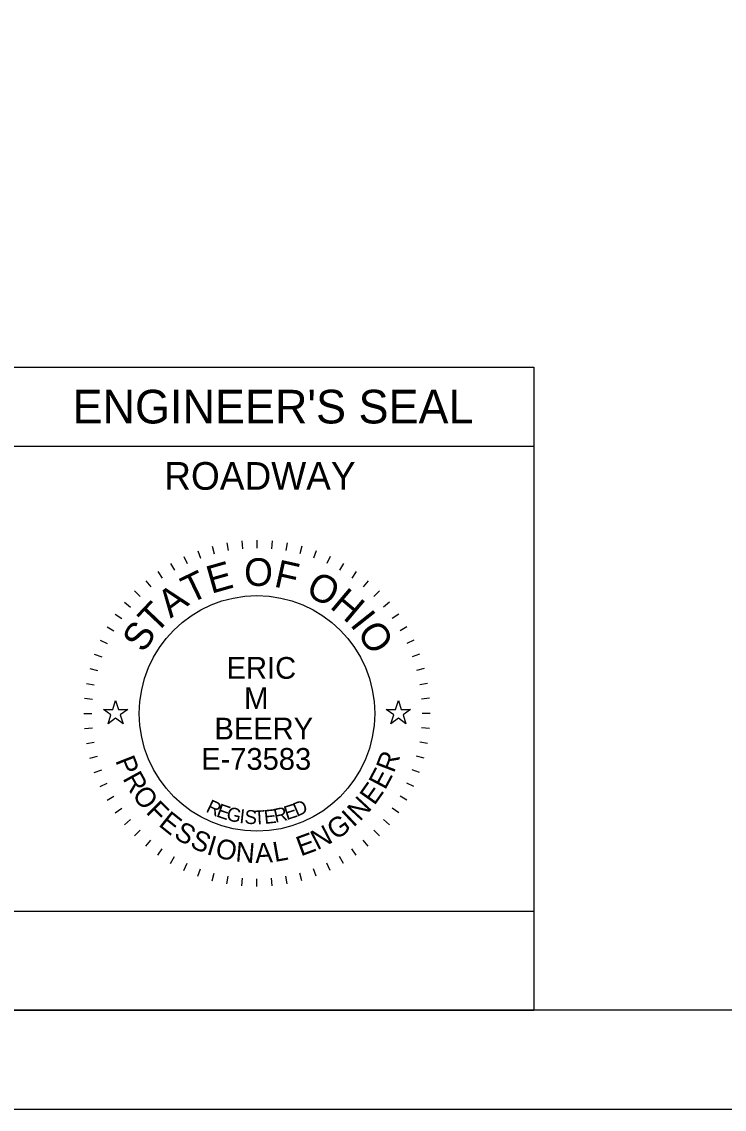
# Model space of a CAD drawing. Extents: x 0 to 34, y 0 to 22.
# Drawn here: x 23.81 to 27.36, y 0 to 5.49 of the extents above; entities that cross this region are included whole.
import ezdxf

# ---------------------------------------------------------------- set-up
doc = ezdxf.new("R2010")
doc.units = 0
for name, color, linetype in [('Default', 7, 'Continuous'), ('SH_Border', 7, 'Continuous'), ('SH_Cut_Line', 7, 'Continuous'), ('SH_Data', 7, 'Continuous')]:
    doc.layers.add(name, color=color, linetype=linetype)

msp = doc.modelspace()

# ---------------------------------------------------------------- linework, layer by layer
at = {"layer": 'Default'}
for points in [[(24.2236, 2.02), (24.2705, 2.02), (24.285, 2.0645), (24.2995, 2.02), (24.3464, 2.02), (24.3085, 1.9924), (24.323, 1.9478), (24.285, 1.9754), (24.247, 1.9478), (24.2615, 1.9924)], [(25.6536, 2.02), (25.7005, 2.02), (25.715, 2.0645), (25.7295, 2.02), (25.7764, 2.02), (25.7385, 1.9924), (25.753, 1.9478), (25.715, 1.9754), (25.677, 1.9478), (25.6915, 1.9924)]]:
    msp.add_lwpolyline(points, close=True, dxfattribs=at)
at = {"layer": 'SH_Border'}
msp.add_lwpolyline([(1.5, 21.5), (33.5, 21.5), (33.5, 0.5), (1.5, 0.5)], close=True, dxfattribs=at)
at = {"layer": 'SH_Cut_Line'}
msp.add_lwpolyline([(0, 0), (34, 0), (34, 22), (0, 22)], close=True, dxfattribs=at)
at = {"layer": 'SH_Data'}
for p, q in [((23.6, 3.75), (26.4, 3.75)), ((26.4, 3.75), (26.4, 0.5)), ((23.6, 3.35), (26.4, 3.35)), ((24.8481, 2.8617), (24.855, 2.8223)), ((24.9237, 2.8717), (24.9272, 2.8318)), ((25, 2.875), (25, 2.835)), ((25.0763, 2.8717), (25.0728, 2.8318)), ((25.1519, 2.8617), (25.145, 2.8223)), ((24.7007, 2.8222), (24.7144, 2.7846)), ((24.7735, 2.8452), (24.7839, 2.8065)), ((25.2265, 2.8452), (25.2161, 2.8065)), ((25.2993, 2.8222), (25.2856, 2.7846)), ((24.5625, 2.7578), (24.5825, 2.7231)), ((24.6302, 2.793), (24.6471, 2.7568)), ((25.3698, 2.793), (25.3529, 2.7568)), ((25.4375, 2.7578), (25.4175, 2.7231)), ((24.4981, 2.7168), (24.5211, 2.684)), ((25.5019, 2.7168), (25.4789, 2.684)), ((24.4376, 2.6703), (24.4633, 2.6396)), ((25.5624, 2.6703), (25.5367, 2.6396)), ((24.3813, 2.6187), (24.4096, 2.5904)), ((25.6187, 2.6187), (25.5904, 2.5904)), ((24.3297, 2.5624), (24.3604, 2.5367)), ((25.6703, 2.5624), (25.6396, 2.5367)), ((24.2832, 2.5019), (24.316, 2.4789)), ((25.7168, 2.5019), (25.684, 2.4789)), ((24.2422, 2.4375), (24.2769, 2.4175)), ((25.7578, 2.4375), (25.7231, 2.4175)), ((24.207, 2.3698), (24.2432, 2.3529)), ((25.793, 2.3698), (25.7568, 2.3529)), ((24.1778, 2.2993), (24.2154, 2.2856)), ((25.8222, 2.2993), (25.7846, 2.2856)), ((24.1548, 2.2265), (24.1935, 2.2161)), ((25.8452, 2.2265), (25.8065, 2.2161)), ((24.1383, 2.1519), (24.1777, 2.145)), ((25.8617, 2.1519), (25.8223, 2.145)), ((24.1283, 2.0763), (24.1682, 2.0728)), ((25.8717, 2.0763), (25.8318, 2.0728)), ((24.125, 2), (24.165, 2)), ((25.875, 2), (25.835, 2)), ((24.1283, 1.9237), (24.1682, 1.9272)), ((25.8717, 1.9237), (25.8318, 1.9272)), ((24.1383, 1.8481), (24.1777, 1.855)), ((25.8617, 1.8481), (25.8223, 1.855)), ((24.1548, 1.7735), (24.1935, 1.7839)), ((25.8452, 1.7735), (25.8065, 1.7839)), ((24.1778, 1.7007), (24.2154, 1.7144)), ((25.8222, 1.7007), (25.7846, 1.7144)), ((24.207, 1.6302), (24.2432, 1.6471)), ((25.793, 1.6302), (25.7568, 1.6471)), ((24.2422, 1.5625), (24.2769, 1.5825)), ((25.7578, 1.5625), (25.7231, 1.5825)), ((24.2832, 1.4981), (24.316, 1.5211)), ((25.7168, 1.4981), (25.684, 1.5211)), ((24.3297, 1.4376), (24.3604, 1.4633)), ((25.6703, 1.4376), (25.6396, 1.4633)), ((24.3813, 1.3813), (24.4096, 1.4096)), ((25.6187, 1.3813), (25.5904, 1.4096)), ((24.4376, 1.3297), (24.4633, 1.3604)), ((25.5624, 1.3297), (25.5367, 1.3604)), ((24.4981, 1.2832), (24.5211, 1.316)), ((24.5625, 1.2422), (24.5825, 1.2769)), ((25.4375, 1.2422), (25.4175, 1.2769)), ((25.5019, 1.2832), (25.4789, 1.316)), ((24.6302, 1.207), (24.6471, 1.2432)), ((24.7007, 1.1778), (24.7144, 1.2154)), ((25.2993, 1.1778), (25.2856, 1.2154)), ((25.3698, 1.207), (25.3529, 1.2432)), ((24.7735, 1.1548), (24.7839, 1.1935)), ((24.8481, 1.1383), (24.855, 1.1777)), ((24.9237, 1.1283), (24.9272, 1.1682)), ((25, 1.125), (25, 1.165)), ((25.0763, 1.1283), (25.0728, 1.1682)), ((25.1519, 1.1383), (25.145, 1.1777)), ((25.2265, 1.1548), (25.2161, 1.1935)), ((23.6, 0.5), (26.4, 0.5))]:
    msp.add_line(p, q, dxfattribs=at)
msp.add_lwpolyline([(23.6, 0.5), (23.6, 1), (26.4, 1), (26.4, 0.5)], close=True, dxfattribs=at)
msp.add_circle((25, 2), 0.595, dxfattribs=at)

# ---------------------------------------------------------------- texts
for s, height, p in [("ENGINEER'S SEAL", 0.17, (24.0676, 3.465)), ('ROADWAY', 0.14, (24.5311, 3.13)), ('ERIC', 0.11, (24.8465, 2.1749)), ('M', 0.11, (24.9348, 2.0216)), ('BEERY', 0.11, (24.7848, 1.8684)), ('E-73583', 0.11, (24.7177, 1.7151))]:
    msp.add_text(s, height=height, dxfattribs=at).set_placement(p)
for s, height, rotation, p in [('E', 0.14, 15.7571, (24.7684, 2.6038)), ('O', 0.14, 359.7812, (24.9347, 2.6443)), ('F', 0.14, 347.4362, (25.0811, 2.6417)), ('T', 0.14, 25.7167, (24.6616, 2.5518)), ('O', 0.14, 332.2586, (25.2398, 2.6015)), ('A', 0.14, 36.4747, (24.5634, 2.4781)), ('H', 0.14, 319.9136, (25.3632, 2.5361)), ('T', 0.14, 46.4344, (24.4883, 2.3964)), ('I', 0.14, 308.367, (25.4665, 2.4483)), ('S', 0.14, 57.1924, (24.4281, 2.3014)), ('O', 0.14, 303.1491, (25.5021, 2.4089)), ('P', 0.1, 291.494, (24.2823, 1.7621)), ('R', 0.1, 69.2322, (25.6919, 1.6954)), ('R', 0.1, 298.7311, (24.319, 1.6717)), ('E', 0.1, 61.9951, (25.6476, 1.6098)), ('E', 0.1, 54.758, (25.5933, 1.5314)), ('O', 0.1, 306.4666, (24.3655, 1.5883)), ('F', 0.1, 314.7068, (24.4343, 1.4983)), ('R', 0.07, 334.487, (24.7375, 1.5051)), ('E', 0.07, 341.04, (24.7906, 1.4801)), ('E', 0.07, 17.6836, (25.1498, 1.4602)), ('D', 0.07, 23.3052, (25.201, 1.477)), ('N', 0.1, 47.0224, (25.5202, 1.4508)), ('E', 0.1, 321.4393, (24.4978, 1.4348)), ('G', 0.07, 347.4752, (24.8414, 1.4618)), ('I', 0.07, 353.7858, (24.9091, 1.4468)), ('S', 0.07, 356.8926, (24.9358, 1.4429)), ('T', 0.07, 3.0061, (24.9857, 1.4387)), ('E', 0.07, 6.0117, (25.0389, 1.4412)), ('R', 0.07, 11.9184, (25.0925, 1.4474)), ('I', 0.1, 43.287, (25.4868, 1.4214)), ('S', 0.1, 328.6764, (24.5743, 1.3752)), ('N', 0.1, 27.3113, (25.3045, 1.3075)), ('G', 0.1, 35.0469, (25.3981, 1.357)), ('S', 0.1, 335.9134, (24.6564, 1.3266)), ('I', 0.1, 343.1505, (24.7406, 1.2897)), ('E', 0.1, 20.0742, (25.2212, 1.277)), ('O', 0.1, 346.8859, (24.7839, 1.2751)), ('N', 0.1, 355.1261, (24.8888, 1.2517)), ('A', 0.1, 2.8617, (24.9923, 1.2437)), ('L', 0.1, 10.0987, (25.0894, 1.249))]:
    msp.add_text(s, height=height, rotation=rotation, dxfattribs=at).set_placement(p)

doc.saveas('drawing.dxf')
